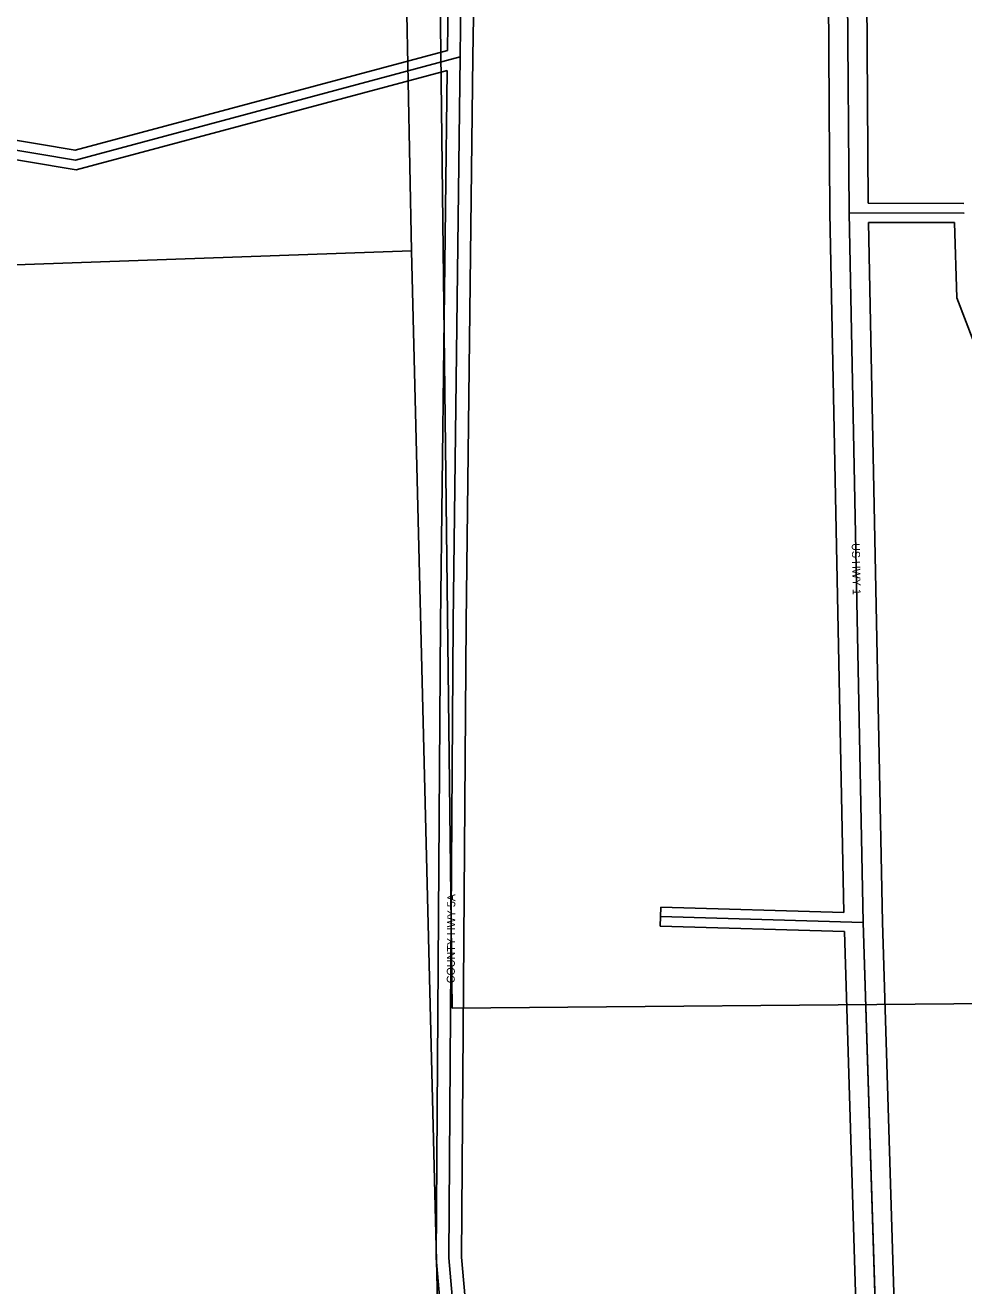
# Model space of a CAD drawing. Extents: x 418523 to 616617, y 1878279 to 2196743.
# Drawn here: x 551209 to 554141, y 2006110 to 2010049 of the extents above; entities that cross this region are included whole.
import ezdxf

# ---------------------------------------------------------------- set-up
doc = ezdxf.new("R2010")
doc.units = 0
for name, color, linetype in [('Level 1', 7, 'Continuous'), ('Level 13', 7, 'Continuous'), ('Level 14', 7, 'Continuous'), ('Level 22', 7, 'Continuous'), ('Level 23', 7, 'Continuous'), ('Level 31', 7, 'Continuous'), ('Level 32', 7, 'Continuous'), ('Level 34', 7, 'Continuous'), ('Level 51', 7, 'Continuous'), ('Level 8', 7, 'Continuous')]:
    doc.layers.add(name, color=color, linetype=linetype)

msp = doc.modelspace()

# ---------------------------------------------------------------- linework, layer by layer
at = {"layer": 'Level 1'}
for p, q in [((552313.778, 2014654.627), (552415.309, 2009343.34)), ((552542.897, 2006977.064), (552458.241, 2014061.206)), ((549743.059, 2009249.671), (552415.309, 2009343.34)), ((552415.309, 2009343.34), (552564.972, 2003346.116)), ((556186.788, 2007010.477), (552542.897, 2006977.064))]:
    msp.add_line(p, q, dxfattribs=at)
at = {"layer": 'Level 13'}
for p, q in [((553783.101, 2009462.728), (553771.802, 2010979.224)), ((553827.318, 2007245.005), (553783.101, 2009462.728)), ((553865.677, 2005994.271), (553827.318, 2007245.005))]:
    msp.add_line(p, q, dxfattribs=at)
at = {"layer": 'Level 14'}
for p, q in [((553723.113, 2009461.532), (553712.049, 2010945.723)), ((553842.883, 2009492.561), (553832.064, 2010944.574)), ((553766.671, 2007276.789), (553723.113, 2009461.532)), ((553887.307, 2007246.2), (553843.717, 2009432.557)), ((553925.681, 2005995.155), (553887.307, 2007246.2)), ((553805.674, 2005993.435), (553768.156, 2007216.719))]:
    msp.add_line(p, q, dxfattribs=at)
at = {"layer": 'Level 22'}
msp.add_line((552567.524, 2009949.453), (552575.95, 2010576.016), dxfattribs=at)
msp.add_lwpolyline([(552556.47, 2005923.038), (552532.201, 2006198.033), (552546.047, 2008182.124), (552567.524, 2009949.453)], dxfattribs=at)
at = {"layer": 'Level 23'}
for p, q in [((552527.794, 2009969.861), (552535.953, 2010576.554)), ((552607.521, 2009948.915), (552615.551, 2010545.996))]:
    msp.add_line(p, q, dxfattribs=at)
for points in [[(552593.989, 2005952.931), (552572.214, 2006199.656), (552586.047, 2008181.741), (552607.521, 2009948.967)], [(552516.502, 2005920.919), (552492.188, 2006196.411), (552506.048, 2008182.507), (552527.01, 2009907.531)]]:
    msp.add_lwpolyline(points, dxfattribs=at)
at = {"layer": 'Level 31'}
for p, q in [((554141.623, 2009461.728), (553783.101, 2009462.728)), ((553827.318, 2007245.005), (553193.654, 2007263.51))]:
    msp.add_line(p, q, dxfattribs=at)
msp.add_lwpolyline([(550757.81, 2009729.149), (551366.149, 2009627.396), (552567.524, 2009949.453)], dxfattribs=at)
at = {"layer": 'Level 32'}
for p, q in [((554141.236, 2009491.728), (553842.882, 2009492.561)), ((554112.516, 2009431.807), (553843.718, 2009432.557)), ((553192.779, 2007233.522), (553194.53, 2007293.497)), ((553766.671, 2007276.788), (553194.53, 2007293.497)), ((553768.156, 2007216.719), (553192.779, 2007233.522))]:
    msp.add_line(p, q, dxfattribs=at)
for points in [[(550762.759, 2009758.739), (551364.674, 2009658.06), (552527.794, 2009969.861)], [(550752.861, 2009699.559), (551367.626, 2009596.731), (552527.01, 2009907.531)], [(554333.769, 2008292.892), (554310.256, 2008720.466), (554220.757, 2008933.117), (554119.629, 2009197.157), (554112.515, 2009431.807)]]:
    msp.add_lwpolyline(points, dxfattribs=at)
at = {"layer": 'Level 8'}
msp.add_lwpolyline([(553866.15, 2005994.342), (553827.128, 2007245.371), (553783.087, 2009462.421), (554142.096, 2009461.426)], dxfattribs=at)

# ---------------------------------------------------------------- texts
at = {"layer": 'Level 34'}
for s, rotation, p in [('US HWY 1', 271.141192, (553791.188, 2008430.14)), ('COUNTY HWY 5A', 89.59915, (552550.681, 2007055.271))]:
    msp.add_text(s, height=25, rotation=rotation, dxfattribs=at).set_placement(p)
at = {"layer": 'Level 51'}
msp.add_text('FLORIDA EAST COAST RAILROAD', height=160, rotation=273.427092, dxfattribs=at).set_placement((550879.951, 2008146.893))

doc.saveas('drawing.dxf')
